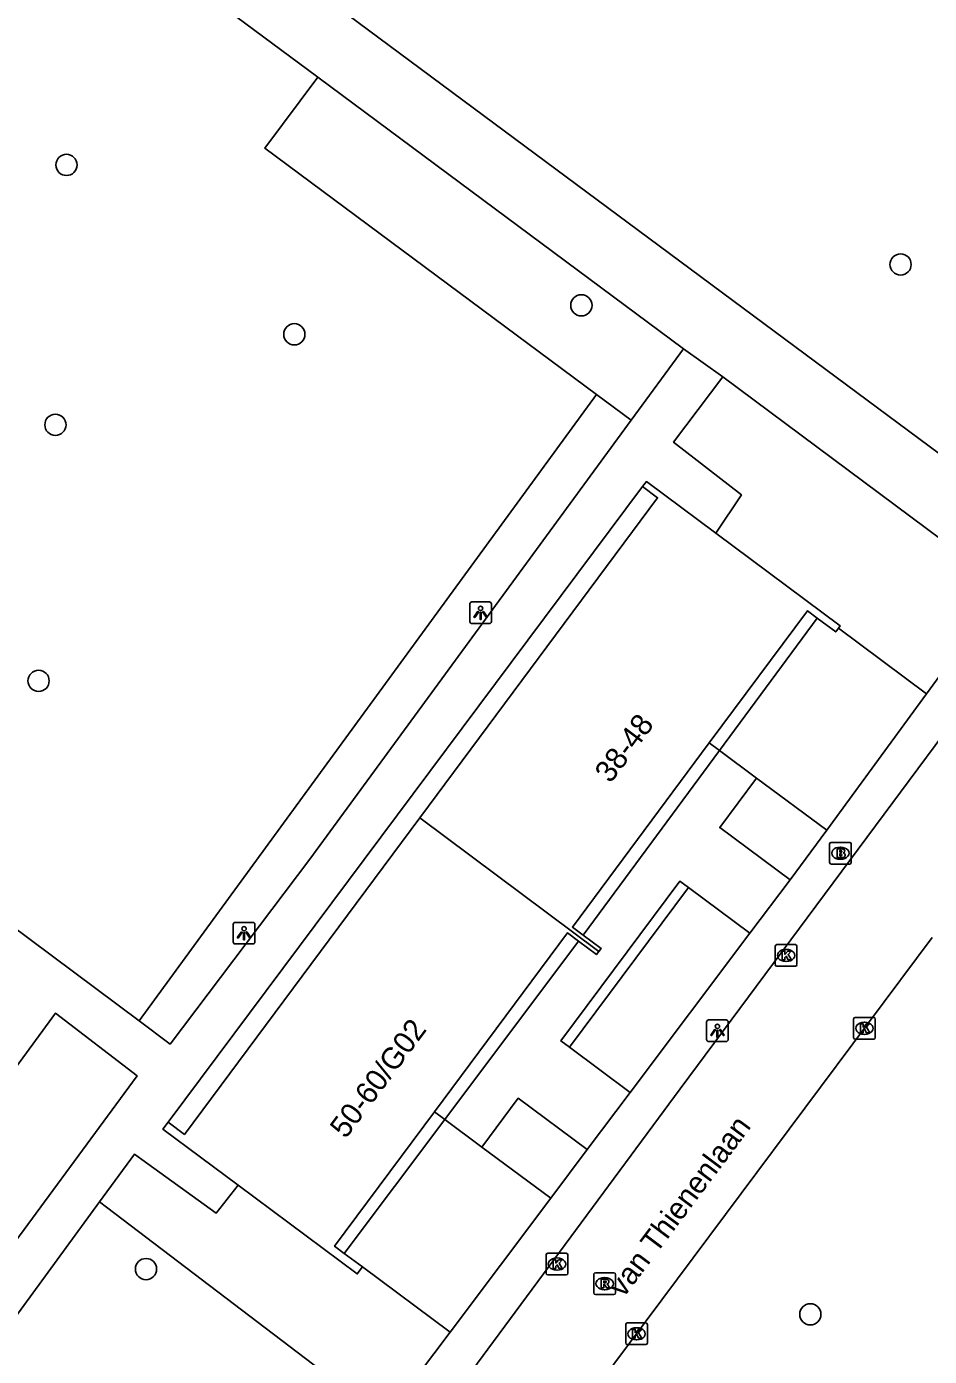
# Model space of a CAD drawing. Extents: x 160026 to 161302, y 384757 to 385701.
# Drawn here: x 160389 to 160430.6, y 385253.6 to 385314.9 of the extents above; entities that cross this region are included whole.
import ezdxf

# ---------------------------------------------------------------- set-up
doc = ezdxf.new("R2010")
doc.units = 0
for name, color, linetype in [('IMGEO_Boom', 7, 'Continuous'), ('IMGEO_Brandkraan', 7, 'Continuous'), ('IMGEO_Groenvoorziening', 7, 'Continuous'), ('IMGEO_Haag', 7, 'Continuous'), ('IMGEO_Kolk', 7, 'Continuous'), ('IMGEO_Lichtpunt', 7, 'Continuous'), ('IMGEO_Openbare_ruimte_label', 7, 'Continuous'), ('IMGEO_Pand', 7, 'Continuous'), ('IMGEO_Pand_nummerreeks', 7, 'Continuous'), ('IMGEO_Rijbaan_lokaal_open', 7, 'Continuous'), ('IMGEO_Rioolput', 7, 'Continuous'), ('IMGEO_Voetpad_open', 7, 'Continuous')]:
    doc.layers.add(name, color=color, linetype=linetype)

msp = doc.modelspace()

# ---------------------------------------------------------------- linework, layer by layer
at = {"layer": 'IMGEO_Boom'}
for centre in [(160390.866, 385308.488), (160429.309, 385303.9), (160414.598, 385302.018), (160401.366, 385300.685), (160390.356, 385296.514), (160389.58, 385284.719), (160394.533, 385257.62), (160425.149, 385255.537)]:
    msp.add_circle(centre, 0.489, dxfattribs=at)
at = {"layer": 'IMGEO_Brandkraan'}
for p, q in [((160426.036, 385276.351), (160426.036, 385277.203)), ((160426.111, 385277.277), (160426.963, 385277.277)), ((160426.524, 385277.057), (160426.549, 385277.057)), ((160427.037, 385277.203), (160427.037, 385276.351)), ((160426.547, 385276.497), (160426.522, 385276.497)), ((160426.963, 385276.277), (160426.111, 385276.277))]:
    msp.add_line(p, q, dxfattribs=at)
for points in [[(160426.036, 385276.351), (160426.036, 385277.203)], [(160426.111, 385277.277), (160426.963, 385277.277)], [(160426.384, 385276.977), (160426.384, 385276.577), (160426.597, 385276.577)], [(160426.615, 385276.977), (160426.384, 385276.977)], [(160427.037, 385277.203), (160427.037, 385276.351)], [(160426.563, 385276.896), (160426.509, 385276.896), (160426.509, 385276.82)], [(160426.509, 385276.82), (160426.562, 385276.82)], [(160426.571, 385276.744), (160426.509, 385276.744), (160426.509, 385276.663)], [(160426.509, 385276.663), (160426.571, 385276.663)], [(160426.963, 385276.277), (160426.111, 385276.277)]]:
    msp.add_lwpolyline(points, dxfattribs=at)
for centre, radius, start, end in [((160426.113, 385277.201), 0.0765, 91.55205, 178.44795), ((160426.113, 385277.201), 0.0765, 91.55205, 178.44795), ((160426.619, 385276.832), 0.145, 59.4692, 91.53667), ((160426.644, 385276.879), 0.0922, 285.51372, 58.15012), ((160426.961, 385277.201), 0.0765, 1.55205, 88.44795), ((160426.961, 385277.201), 0.0765, 1.55205, 88.44795), ((160426.113, 385276.353), 0.0765, 181.55205, 268.44795), ((160426.113, 385276.353), 0.0765, 181.55205, 268.44795), ((160426.564, 385276.858), 0.0379, 267.82845, 90.93552), ((160426.572, 385276.703), 0.0404, 269.87594, 90.50774), ((160426.603, 385276.828), 0.251, 268.66757, 293.53466), ((160426.649, 385276.687), 0.105, 301.31148, 78.98903), ((160426.961, 385276.353), 0.0765, 271.55205, 358.44795), ((160426.961, 385276.353), 0.0765, 271.55205, 358.44795)]:
    msp.add_arc(centre, radius, start, end, dxfattribs=at)
for centre, major_axis, ratio, start_param, end_param in [((160426.523, 385276.777), (-0.387, 0.002), 0.722429, 4.712389, 7.853982), ((160426.548, 385276.777), (-0.39, 0.002), 0.717154, 1.570796, 4.712389)]:
    msp.add_ellipse(centre, major_axis=major_axis, ratio=ratio, start_param=start_param, end_param=end_param, dxfattribs=at)
at = {"layer": 'IMGEO_Groenvoorziening'}
for points in [[(160402.452, 385312.526), (160400.011, 385309.258), (160415.293, 385297.914)], [(160392.388, 385260.712), (160392.706, 385260.479), (160405.539, 385250.725)]]:
    msp.add_lwpolyline(points, dxfattribs=at)
at = {"layer": 'IMGEO_Haag'}
for points in [[(160415.293, 385297.914), (160405.856, 385284.994), (160394.21, 385269.049)], [(160415.293, 385297.914), (160416.894, 385296.725)], [(160414.049, 385267.836), (160419.531, 385275.199)]]:
    msp.add_lwpolyline(points, dxfattribs=at)
at = {"layer": 'IMGEO_Kolk'}
for p, q in [((160423.532, 385271.644), (160423.532, 385272.496)), ((160423.607, 385272.57), (160424.459, 385272.57)), ((160424.02, 385272.35), (160424.045, 385272.35)), ((160424.533, 385272.496), (160424.533, 385271.644)), ((160424.459, 385271.57), (160423.607, 385271.57)), ((160424.043, 385271.79), (160424.018, 385271.79)), ((160427.143, 385268.285), (160427.143, 385269.137)), ((160427.218, 385269.211), (160428.07, 385269.211)), ((160427.631, 385268.991), (160427.656, 385268.991)), ((160428.144, 385269.137), (160428.144, 385268.285)), ((160427.654, 385268.431), (160427.629, 385268.431)), ((160428.07, 385268.211), (160427.218, 385268.211)), ((160412.974, 385257.425), (160412.974, 385258.277)), ((160413.049, 385258.351), (160413.901, 385258.351)), ((160413.462, 385258.131), (160413.487, 385258.131)), ((160413.975, 385258.277), (160413.975, 385257.425)), ((160413.901, 385257.351), (160413.049, 385257.351)), ((160413.485, 385257.571), (160413.46, 385257.571)), ((160416.64, 385254.215), (160416.64, 385255.067)), ((160416.715, 385255.141), (160417.567, 385255.141)), ((160417.128, 385254.921), (160417.153, 385254.921)), ((160417.641, 385255.067), (160417.641, 385254.215)), ((160417.151, 385254.361), (160417.126, 385254.361)), ((160417.567, 385254.141), (160416.715, 385254.141))]:
    msp.add_line(p, q, dxfattribs=at)
for points in [[(160423.532, 385271.644), (160423.532, 385272.496)], [(160423.607, 385272.57), (160424.459, 385272.57)], [(160423.853, 385272.27), (160423.976, 385272.27), (160423.976, 385272.119), (160424.106, 385272.27), (160424.27, 385272.27), (160424.124, 385272.119), (160424.277, 385271.87), (160424.125, 385271.87), (160424.04, 385272.034), (160423.976, 385271.967), (160423.976, 385271.87), (160423.853, 385271.87), (160423.853, 385272.27)], [(160424.533, 385272.496), (160424.533, 385271.644)], [(160424.459, 385271.57), (160423.607, 385271.57)], [(160427.143, 385268.285), (160427.143, 385269.137)], [(160427.218, 385269.211), (160428.07, 385269.211)], [(160428.144, 385269.137), (160428.144, 385268.285)], [(160427.464, 385268.911), (160427.587, 385268.911), (160427.587, 385268.76), (160427.717, 385268.911), (160427.881, 385268.911), (160427.735, 385268.76), (160427.888, 385268.511), (160427.736, 385268.511), (160427.651, 385268.675), (160427.587, 385268.608), (160427.587, 385268.511), (160427.464, 385268.511), (160427.464, 385268.911)], [(160428.07, 385268.211), (160427.218, 385268.211)], [(160412.974, 385257.425), (160412.974, 385258.277)], [(160413.049, 385258.351), (160413.901, 385258.351)], [(160413.295, 385258.051), (160413.418, 385258.051), (160413.418, 385257.9), (160413.548, 385258.051), (160413.712, 385258.051), (160413.566, 385257.9), (160413.719, 385257.651), (160413.567, 385257.651), (160413.482, 385257.815), (160413.418, 385257.748), (160413.418, 385257.651), (160413.295, 385257.651), (160413.295, 385258.051)], [(160413.975, 385258.277), (160413.975, 385257.425)], [(160413.901, 385257.351), (160413.049, 385257.351)], [(160416.64, 385254.215), (160416.64, 385255.067)], [(160416.715, 385255.141), (160417.567, 385255.141)], [(160417.641, 385255.067), (160417.641, 385254.215)], [(160416.961, 385254.841), (160417.084, 385254.841), (160417.084, 385254.69), (160417.214, 385254.841), (160417.378, 385254.841), (160417.232, 385254.69), (160417.385, 385254.441), (160417.233, 385254.441), (160417.148, 385254.605), (160417.084, 385254.538), (160417.084, 385254.441), (160416.961, 385254.441), (160416.961, 385254.841)], [(160417.567, 385254.141), (160416.715, 385254.141)]]:
    msp.add_lwpolyline(points, dxfattribs=at)
for centre, start, end in [((160423.609, 385272.494), 91.55205, 178.44795), ((160423.609, 385272.494), 91.55205, 178.44795), ((160424.457, 385272.494), 1.55205, 88.44795), ((160424.457, 385272.494), 1.55205, 88.44795), ((160423.609, 385271.646), 181.55205, 268.44795), ((160423.609, 385271.646), 181.55205, 268.44795), ((160424.457, 385271.646), 271.55205, 358.44795), ((160424.457, 385271.646), 271.55205, 358.44795), ((160427.22, 385269.135), 91.55205, 178.44795), ((160427.22, 385269.135), 91.55205, 178.44795), ((160428.068, 385269.135), 1.55205, 88.44795), ((160428.068, 385269.135), 1.55205, 88.44795), ((160427.22, 385268.287), 181.55205, 268.44795), ((160427.22, 385268.287), 181.55205, 268.44795), ((160428.068, 385268.287), 271.55205, 358.44795), ((160428.068, 385268.287), 271.55205, 358.44795), ((160413.051, 385258.275), 91.55205, 178.44795), ((160413.051, 385258.275), 91.55205, 178.44795), ((160413.899, 385258.275), 1.55205, 88.44795), ((160413.899, 385258.275), 1.55205, 88.44795), ((160413.051, 385257.427), 181.55205, 268.44795), ((160413.051, 385257.427), 181.55205, 268.44795), ((160413.899, 385257.427), 271.55205, 358.44795), ((160413.899, 385257.427), 271.55205, 358.44795), ((160416.717, 385255.065), 91.55205, 178.44795), ((160416.717, 385255.065), 91.55205, 178.44795), ((160417.565, 385255.065), 1.55205, 88.44795), ((160417.565, 385255.065), 1.55205, 88.44795), ((160416.717, 385254.217), 181.55205, 268.44795), ((160416.717, 385254.217), 181.55205, 268.44795), ((160417.565, 385254.217), 271.55205, 358.44795), ((160417.565, 385254.217), 271.55205, 358.44795)]:
    msp.add_arc(centre, 0.0765, start, end, dxfattribs=at)
for centre, major_axis, ratio, start_param, end_param in [((160424.019, 385272.07), (-0.387, 0.002), 0.722429, 4.712389, 7.853982), ((160424.044, 385272.07), (-0.39, 0.002), 0.717154, 1.570796, 4.712389), ((160427.63, 385268.711), (-0.387, 0.002), 0.722429, 4.712389, 7.853982), ((160427.655, 385268.711), (-0.39, 0.002), 0.717154, 1.570796, 4.712389), ((160413.461, 385257.851), (-0.387, 0.002), 0.722429, 4.712389, 7.853982), ((160413.486, 385257.851), (-0.39, 0.002), 0.717154, 1.570796, 4.712389), ((160417.127, 385254.641), (-0.387, 0.002), 0.722429, 4.712389, 7.853982), ((160417.152, 385254.641), (-0.39, 0.002), 0.717154, 1.570796, 4.712389)]:
    msp.add_ellipse(centre, major_axis=major_axis, ratio=ratio, start_param=start_param, end_param=end_param, dxfattribs=at)
at = {"layer": 'IMGEO_Lichtpunt'}
for p, q in [((160409.455, 385288.258), (160409.455, 385287.451)), ((160409.455, 385288.258), (160409.455, 385287.451)), ((160410.357, 385288.353), (160409.549, 385288.353)), ((160410.357, 385288.353), (160409.549, 385288.353)), ((160410.451, 385287.451), (160410.451, 385288.258)), ((160410.451, 385287.451), (160410.451, 385288.258)), ((160409.549, 385287.357), (160410.357, 385287.357)), ((160409.549, 385287.357), (160410.357, 385287.357)), ((160398.552, 385273.498), (160398.552, 385272.691)), ((160398.552, 385273.498), (160398.552, 385272.691)), ((160399.454, 385273.593), (160398.646, 385273.593)), ((160399.454, 385273.593), (160398.646, 385273.593)), ((160399.548, 385272.691), (160399.548, 385273.498)), ((160399.548, 385272.691), (160399.548, 385273.498)), ((160398.646, 385272.597), (160399.454, 385272.597)), ((160398.646, 385272.597), (160399.454, 385272.597)), ((160420.37, 385269.002), (160420.37, 385268.195)), ((160420.37, 385269.002), (160420.37, 385268.195)), ((160421.272, 385269.097), (160420.464, 385269.097)), ((160421.272, 385269.097), (160420.464, 385269.097)), ((160421.366, 385268.195), (160421.366, 385269.002)), ((160421.366, 385268.195), (160421.366, 385269.002)), ((160420.464, 385268.101), (160421.272, 385268.101)), ((160420.464, 385268.101), (160421.272, 385268.101))]:
    msp.add_line(p, q, dxfattribs=at)
for points in [[(160409.829, 385287.922), (160409.868, 385287.894), (160409.68, 385287.632), (160409.642, 385287.659), (160409.829, 385287.922)], [(160409.931, 385287.874), (160409.978, 385287.874), (160409.978, 385287.552), (160409.931, 385287.552), (160409.931, 385287.874)], [(160410.041, 385287.894), (160410.079, 385287.921), (160410.266, 385287.659), (160410.227, 385287.631), (160410.041, 385287.894)], [(160398.926, 385273.162), (160398.965, 385273.134), (160398.777, 385272.872), (160398.739, 385272.899), (160398.926, 385273.162)], [(160399.028, 385273.114), (160399.075, 385273.114), (160399.075, 385272.792), (160399.028, 385272.792), (160399.028, 385273.114)], [(160399.138, 385273.134), (160399.176, 385273.161), (160399.363, 385272.899), (160399.324, 385272.871), (160399.138, 385273.134)], [(160420.744, 385268.666), (160420.783, 385268.638), (160420.595, 385268.376), (160420.557, 385268.403), (160420.744, 385268.666)], [(160420.846, 385268.618), (160420.893, 385268.618), (160420.893, 385268.296), (160420.846, 385268.296), (160420.846, 385268.618)], [(160420.956, 385268.638), (160420.994, 385268.665), (160421.181, 385268.403), (160421.142, 385268.375), (160420.956, 385268.638)]]:
    msp.add_lwpolyline(points, dxfattribs=at)
for centre in [(160409.954, 385288.056), (160399.051, 385273.296), (160420.869, 385268.8)]:
    msp.add_circle(centre, 0.0994, dxfattribs=at)
for centre, start, end in [((160409.549, 385288.258), 90, 180), ((160409.549, 385288.258), 90, 180), ((160410.357, 385288.258), 0, 90), ((160410.357, 385288.258), 0, 90), ((160409.549, 385287.451), 180, 270), ((160409.549, 385287.451), 180, 270), ((160410.357, 385287.451), 270, 0), ((160410.357, 385287.451), 270, 360), ((160398.646, 385273.498), 90, 180), ((160398.646, 385273.498), 90, 180), ((160399.454, 385273.498), 0, 90), ((160399.454, 385273.498), 0, 90), ((160398.646, 385272.691), 180, 270), ((160398.646, 385272.691), 180, 270), ((160399.454, 385272.691), 270, 0), ((160399.454, 385272.691), 270, 360), ((160420.464, 385269.002), 90, 180), ((160420.464, 385269.002), 90, 180), ((160421.272, 385269.002), 0, 90), ((160421.272, 385269.002), 0, 90), ((160420.464, 385268.195), 180, 270), ((160420.464, 385268.195), 180, 270), ((160421.272, 385268.195), 270, 0), ((160421.272, 385268.195), 270, 360)]:
    msp.add_arc(centre, 0.0946, start, end, dxfattribs=at)
at = {"layer": 'IMGEO_Pand'}
for points in [[(160417.422, 385293.665), (160418.106, 385293.157), (160407.146, 385278.415)], [(160420.792, 385291.519), (160417.594, 385293.897), (160417.422, 385293.665)], [(160426.448, 385287.143), (160426.53, 385287.253), (160420.792, 385291.519)], [(160420.494, 385281.862), (160425.015, 385287.944), (160425.469, 385287.607)], [(160425.469, 385287.607), (160426.322, 385286.972), (160426.448, 385287.143)], [(160414.686, 385273.004), (160414.185, 385273.376), (160420.494, 385281.862)], [(160407.146, 385278.415), (160396.3, 385263.826), (160395.55, 385264.384)], [(160415.4, 385272.251), (160407.146, 385278.415)], [(160407.829, 385264.867), (160413.952, 385273.104), (160414.47, 385272.719)], [(160414.47, 385272.719), (160415.293, 385272.107), (160415.4, 385272.251)], [(160415.4, 385272.251), (160415.506, 385272.394), (160414.686, 385273.004)], [(160403.666, 385258.341), (160403.222, 385258.671), (160407.829, 385264.867)], [(160395.55, 385264.384), (160395.309, 385264.06), (160398.778, 385261.481)], [(160398.778, 385261.481), (160404.271, 385257.398), (160404.507, 385257.716)], [(160404.507, 385257.716), (160403.666, 385258.341)]]:
    msp.add_lwpolyline(points, dxfattribs=at)
at = {"layer": 'IMGEO_Rijbaan_lokaal_open'}
for points in [[(160435.504, 385287.862), (160432.461, 385283.83), (160419.151, 385265.926), (160405.248, 385247.11), (160401.722, 385242.347), (160400.915, 385241.255)], [(160420.967, 385281.51), (160425.469, 385287.607)], [(160430.511, 385284.122), (160426.448, 385287.143)], [(160425.914, 385277.833), (160430.511, 385284.122)], [(160420.494, 385281.862), (160420.967, 385281.51)], [(160420.967, 385281.51), (160422.673, 385280.242)], [(160422.673, 385280.242), (160425.914, 385277.833)], [(160430.766, 385272.898), (160416.095, 385253.243), (160415.954, 385253.054)], [(160408.304, 385264.514), (160407.829, 385264.867)], [(160408.304, 385264.514), (160403.666, 385258.341)], [(160410.015, 385263.242), (160408.304, 385264.514)], [(160413.185, 385260.885), (160410.015, 385263.242)], [(160408.543, 385254.716), (160413.185, 385260.885)], [(160404.507, 385257.716), (160408.543, 385254.716)]]:
    msp.add_lwpolyline(points, dxfattribs=at)
at = {"layer": 'IMGEO_Rioolput'}
for p, q in [((160415.169, 385256.524), (160415.169, 385257.376)), ((160415.244, 385257.45), (160416.096, 385257.45)), ((160416.17, 385257.376), (160416.17, 385256.524)), ((160415.657, 385257.23), (160415.682, 385257.23)), ((160416.096, 385256.45), (160415.244, 385256.45)), ((160415.68, 385256.67), (160415.655, 385256.67))]:
    msp.add_line(p, q, dxfattribs=at)
for points in [[(160415.169, 385256.524), (160415.169, 385257.376)], [(160415.244, 385257.45), (160416.096, 385257.45)], [(160416.17, 385257.376), (160416.17, 385256.524)], [(160415.758, 385257.148), (160415.506, 385257.15), (160415.506, 385256.75)], [(160415.506, 385256.75), (160415.63, 385256.75), (160415.63, 385256.912), (160415.641, 385256.912)], [(160415.684, 385257.069), (160415.63, 385257.069), (160415.63, 385256.988)], [(160415.63, 385256.988), (160415.682, 385256.988)], [(160415.688, 385256.883), (160415.759, 385256.75), (160415.899, 385256.75), (160415.834, 385256.876)], [(160416.096, 385256.45), (160415.244, 385256.45)]]:
    msp.add_lwpolyline(points, dxfattribs=at)
for centre, radius, start, end in [((160415.246, 385257.374), 0.0765, 91.55205, 178.44795), ((160415.246, 385257.374), 0.0765, 91.55205, 178.44795), ((160416.094, 385257.374), 0.0765, 1.55205, 88.44795), ((160416.094, 385257.374), 0.0765, 1.55205, 88.44795), ((160415.64, 385256.859), 0.0533, 26.02933, 88.69889), ((160415.666, 385257.177), 0.19, 274.7715, 282.96867), ((160415.69, 385256.973), 0.0964, 77.00612, 93.18647), ((160415.704, 385257.03), 0.0378, 276.66336, 79.67722), ((160415.757, 385257.038), 0.109, 350.36119, 89.41601), ((160415.755, 385257.038), 0.112, 277.58423, 350.98172), ((160415.739, 385256.823), 0.108, 29.51342, 73.79051), ((160415.246, 385256.526), 0.0765, 181.55205, 268.44795), ((160415.246, 385256.526), 0.0765, 181.55205, 268.44795), ((160416.094, 385256.526), 0.0765, 271.55205, 358.44795), ((160416.094, 385256.526), 0.0765, 271.55205, 358.44795)]:
    msp.add_arc(centre, radius, start, end, dxfattribs=at)
for centre, major_axis, ratio, start_param, end_param in [((160415.656, 385256.95), (-0.387, 0.002), 0.722429, 4.712389, 7.853982), ((160415.681, 385256.95), (-0.39, 0.002), 0.717154, 1.570796, 4.712389)]:
    msp.add_ellipse(centre, major_axis=major_axis, ratio=ratio, start_param=start_param, end_param=end_param, dxfattribs=at)
at = {"layer": 'IMGEO_Voetpad_open'}
for points in [[(160469.141, 385272.846), (160464.832, 385276.029), (160451.586, 385285.854), (160440.214, 385288.427), (160375.119, 385336.693), (160360.892, 385347.448)], [(160390.707, 385321.238), (160402.452, 385312.526)], [(160402.452, 385312.526), (160419.309, 385300.022)], [(160394.21, 385269.049), (160339.974, 385309.507)], [(160419.309, 385300.022), (160416.894, 385296.725)], [(160419.309, 385300.022), (160421.112, 385298.718)], [(160420.792, 385291.519), (160421.971, 385293.287), (160418.845, 385295.714), (160421.112, 385298.718)], [(160421.112, 385298.718), (160434.116, 385289.055)], [(160416.894, 385296.725), (160402.086, 385276.507), (160395.643, 385267.985), (160394.21, 385269.049)], [(160417.422, 385293.665), (160395.55, 385264.384)], [(160434.116, 385289.055), (160430.511, 385284.122)], [(160414.686, 385273.004), (160420.967, 385281.51)], [(160424.216, 385275.547), (160420.973, 385277.958), (160422.673, 385280.242)], [(160425.914, 385277.833), (160424.216, 385275.547)], [(160414.049, 385267.836), (160413.655, 385268.129), (160419.137, 385275.492), (160419.531, 385275.199)], [(160419.531, 385275.199), (160422.368, 385273.091)], [(160422.368, 385273.091), (160424.216, 385275.547)], [(160408.304, 385264.514), (160414.47, 385272.719)], [(160422.368, 385273.091), (160416.849, 385265.755)], [(160387.145, 385257.063), (160394.118, 385266.517), (160390.361, 385269.413), (160386.118, 385263.63), (160384.836, 385264.597)], [(160416.849, 385265.755), (160414.049, 385267.836)], [(160410.015, 385263.242), (160411.687, 385265.487), (160414.868, 385263.122)], [(160414.868, 385263.122), (160416.849, 385265.755)], [(160392.388, 385260.712), (160394.004, 385262.915), (160394.336, 385262.674), (160397.763, 385260.19), (160398.778, 385261.481)], [(160414.868, 385263.122), (160413.185, 385260.885)], [(160384.978, 385250.606), (160392.388, 385260.712)], [(160408.543, 385254.716), (160405.539, 385250.725)]]:
    msp.add_lwpolyline(points, dxfattribs=at)

# ---------------------------------------------------------------- texts
at = {"layer": 'IMGEO_Openbare_ruimte_label'}
msp.add_text('van Thienenlaan', height=1, rotation=53.2562, dxfattribs=at).set_placement((160416.541, 385256.267))
at = {"layer": 'IMGEO_Pand_nummerreeks'}
for s, rotation, p in [('38-48', 53.37251, (160415.941, 385279.962)), ('50-60/G02', 53.37159, (160403.735, 385263.585))]:
    msp.add_text(s, height=1, rotation=rotation, dxfattribs=at).set_placement(p)

doc.saveas('drawing.dxf')
